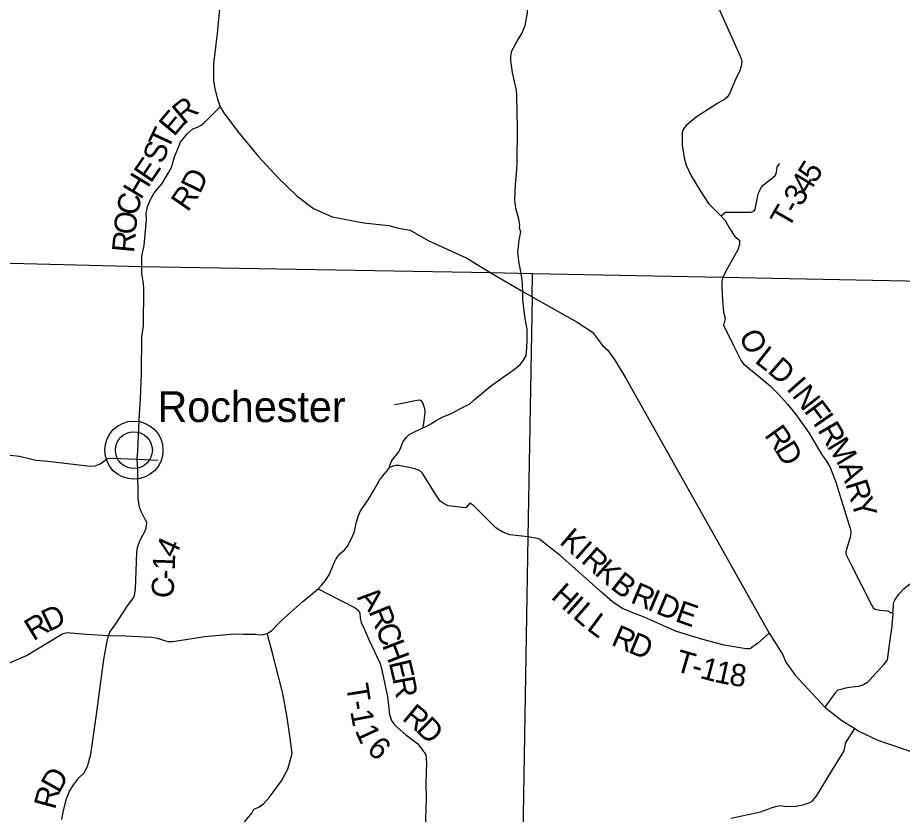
# Model space of a CAD drawing. Extents: x -22 to 431, y -18 to 160.
# Drawn here: x 324.965 to 327.228, y 151.4 to 153.438 of the extents above; entities that cross this region are included whole.
import ezdxf

# ---------------------------------------------------------------- set-up
doc = ezdxf.new("R2010")
doc.units = 0
for name, color, linetype in [('GM_X_Adjacent_County', 7, 'Continuous'), ('GM_X_Adjacent_County_Text', 7, 'Continuous'), ('GM_X_City_Street', 7, 'Continuous'), ('GM_X_City_Street_Text', 7, 'Continuous'), ('GM_X_County_Road', 7, 'Continuous'), ('GM_X_County_ROW', 7, 'Continuous'), ('GM_X_Major_River_Text', 7, 'Continuous'), ('GM_X_Minor_River_Text', 7, 'Continuous'), ('GM_X_Township_Road', 7, 'Continuous')]:
    doc.layers.add(name, color=color, linetype=linetype)

msp = doc.modelspace()

# ---------------------------------------------------------------- linework, layer by layer
at = {"layer": 'GM_X_Adjacent_County_Text'}
for points in [[(326.2484, 152.8999), (326.2484, 152.9001), (326.2493, 152.9074), (326.2474, 152.9225), (326.2394, 152.9506), (326.2367, 152.9711), (326.2382, 153.0116), (326.2416, 153.0492), (326.2427, 153.0666), (326.2434, 153.1561), (326.2422, 153.238), (326.2407, 153.2521), (326.2308, 153.2979), (326.2262, 153.3275), (326.2262, 153.3396), (326.2289, 153.3537), (326.2425, 153.3783), (326.2546, 153.3973), (326.2633, 153.4182), (326.2689, 153.4508), (326.2715, 153.5187)], [(326.7581, 153.4619), (326.8097, 153.3476), (326.8159, 153.3333), (326.8171, 153.3272), (326.8167, 153.3196), (326.8131, 153.3044), (326.8015, 153.28), (326.7854, 153.2431), (326.7802, 153.2351), (326.7734, 153.229), (326.756, 153.2194), (326.7009, 153.1837), (326.6752, 153.1623), (326.6685, 153.1539), (326.6644, 153.144), (326.665, 153.1125), (326.6698, 153.0799), (326.6748, 153.0609), (326.6875, 153.0337), (326.7114, 152.994), (326.7321, 152.9626), (326.7634, 152.9314), (326.7745, 152.9193), (326.7868, 152.8978), (326.7998, 152.8785), (326.8111, 152.8687), (326.8111, 152.8582), (326.8071, 152.8443), (326.7762, 152.7899), (326.769, 152.7734), (326.7658, 152.7641), (326.7659, 152.7611)], [(325.2831, 152.7841), (325.283, 152.7847), (325.2828, 152.8006), (325.2831, 152.828), (325.2889, 152.8551), (325.295, 152.9211), (325.2943, 152.9374), (325.2977, 152.9549), (325.3052, 152.9731), (325.3139, 152.9883), (325.3238, 153.0008), (325.3344, 153.0137), (325.3521, 153.0433), (325.3589, 153.0551), (325.3665, 153.082), (325.382, 153.1196), (325.399, 153.1409), (325.4134, 153.1538), (325.4255, 153.1584), (325.4342, 153.1633), (325.4422, 153.1694), (325.4607, 153.1876), (325.4834, 153.2104)], [(326.2571, 152.7373), (326.2557, 152.7679), (326.2533, 152.7838), (326.2475, 152.8104), (326.2447, 152.8372), (326.248, 152.8688), (326.2518, 152.8903), (326.2484, 152.8999)], [(325.1975, 151.8578), (325.2009, 151.8658), (325.216, 151.8878), (325.2448, 151.9307), (325.2618, 151.9543), (325.2644, 151.9596), (325.2663, 151.9759), (325.27, 152.07), (325.2719, 152.0825), (325.2776, 152.0996), (325.2931, 152.1285), (325.2946, 152.1379), (325.2953, 152.1467), (325.2915, 152.1546), (325.2809, 152.1747), (325.2771, 152.1857), (325.2733, 152.2088), (325.2725, 152.2828), (325.2709, 152.3086), (325.2724, 152.3298), (325.2765, 152.4243), (325.2791, 152.4611), (325.2821, 152.5282), (325.2824, 152.6215), (325.2872, 152.65), (325.2878, 152.7445), (325.2872, 152.7576), (325.2857, 152.7684), (325.2831, 152.7841)], [(326.7659, 152.7611), (326.7661, 152.747), (326.7676, 152.7151), (326.7702, 152.6846), (326.7743, 152.6689), (326.7704, 152.6513), (326.7961, 152.5991), (326.815, 152.5617), (326.8208, 152.5534), (326.836, 152.5406), (326.8601, 152.5214), (326.8902, 152.4962), (326.9112, 152.4751), (326.9338, 152.4494), (326.9552, 152.423), (326.9897, 152.3754), (327.0109, 152.3383), (327.0231, 152.3187), (327.0339, 152.304), (327.0431, 152.2873), (327.0574, 152.2502), (327.0947, 152.1313), (327.0959, 152.1233), (327.0952, 152.1116), (327.0852, 152.0785), (327.0834, 152.0712), (327.0834, 152.0655), (327.0953, 152.0417), (327.1501, 151.9345)], [(326.261, 152.6875), (326.2573, 152.7179), (326.2571, 152.7373)], [(325.1975, 151.8578), (325.2426, 151.8564), (325.2895, 151.8546), (325.3077, 151.8534), (325.3228, 151.8504), (325.3384, 151.8455), (325.3497, 151.8425), (325.3611, 151.8421), (325.4065, 151.8487), (325.4429, 151.8552), (325.491, 151.859), (325.5209, 151.8617), (325.5428, 151.8614), (325.5731, 151.8607), (325.5845, 151.8592), (325.5947, 151.8603), (325.603, 151.863), (325.6144, 151.8698), (325.6386, 151.8942), (325.6651, 151.9185), (325.6942, 151.9447), (325.7336, 151.977), (325.7426, 151.9865), (325.7529, 151.9979), (325.7616, 152.0131), (325.7755, 152.0454), (325.7797, 152.0537), (325.7831, 152.059), (325.7895, 152.0666), (325.8016, 152.078), (325.8088, 152.0864), (325.8175, 152.1027), (325.8258, 152.1213), (325.8322, 152.1482), (325.8368, 152.1646), (325.8417, 152.1763), (325.8614, 152.2044), (325.8757, 152.2276), (325.8859, 152.2454), (325.8908, 152.2553), (325.8984, 152.2655), (325.9098, 152.2777), (325.9166, 152.2876), (325.9169, 152.2929), (325.9226, 152.3054), (325.94, 152.3278), (325.9434, 152.3343), (325.9506, 152.3521), (325.9589, 152.3639), (325.9661, 152.3718), (325.982, 152.3791), (326.0024, 152.3893), (326.0134, 152.3943), (326.0357, 152.408), (326.0513, 152.4163), (326.0638, 152.4217), (326.0751, 152.4259), (326.0887, 152.4331), (326.0974, 152.4384), (326.1114, 152.4449), (326.1205, 152.4494), (326.1326, 152.4601), (326.1735, 152.4943), (326.2042, 152.5171), (326.2352, 152.538), (326.2507, 152.5505), (326.2575, 152.5596), (326.2657, 152.5742), (326.2676, 152.5933), (326.2686, 152.6144), (326.2686, 152.6411), (326.2633, 152.6684), (326.261, 152.6875)], [(324.9387, 152.32), (324.9698, 152.3164), (324.9983, 152.3097), (325.012, 152.3061), (325.042, 152.3033), (325.1513, 152.2912), (325.1637, 152.2914), (325.1762, 152.2966), (325.1889, 152.3063), (325.1949, 152.3102), (325.2073, 152.3116), (325.2709, 152.3086)], [(325.2709, 152.3086), (325.3234, 152.3062)], [(327.1501, 151.9345), (327.1503, 151.934), (327.1507, 151.9331), (327.1542, 151.9278), (327.1584, 151.9252), (327.1702, 151.9223), (327.1895, 151.9205), (327.1926, 151.9198), (327.1979, 151.9168), (327.2032, 151.9145), (327.2029, 151.9031), (327.1997, 151.8758), (327.1951, 151.8408), (327.19, 151.8017), (327.1886, 151.7956), (327.1799, 151.7822), (327.1446, 151.744), (327.1366, 151.7364), (327.1287, 151.7317), (327.1158, 151.7275), (327.0984, 151.7255), (327.0821, 151.7227), (327.0708, 151.7199), (327.0632, 151.7176), (327.0556, 151.7107), (327.0294, 151.6744)], [(324.9363, 151.7846), (324.9882, 151.8067), (325.0786, 151.8611), (325.082, 151.8626), (325.0919, 151.8656), (325.1407, 151.8608), (325.1975, 151.8578)], [(325.0783, 151.3868), (325.0824, 151.4096), (325.09, 151.4399), (325.0979, 151.4597), (325.1093, 151.4768), (325.1221, 151.4935), (325.135, 151.5064), (325.144, 151.5227), (325.1527, 151.5539), (325.167, 151.6552), (325.1854, 151.7964), (325.1941, 151.843), (325.1975, 151.8578)]]:
    msp.add_lwpolyline(points, dxfattribs=at)
at = {"layer": 'GM_X_County_Road'}
msp.add_lwpolyline([(326.0048, 151.5589), (326.0092, 151.5525), (326.0112, 151.5321), (326.0093, 151.4812), (326.0104, 151.4402), (326.0075, 151.362), (326.0046, 151.2439), (325.9988, 151.0556), (326.0007, 151.0484), (326.0114, 151.0379), (326.0437, 151.0196), (326.0464, 151.018), (326.05, 151.0153)], dxfattribs=at)
at = {"layer": 'GM_X_County_ROW'}
msp.add_lwpolyline([(325.4814, 153.4613), (325.4752, 153.3978), (325.466, 153.3204), (325.4665, 153.2778), (325.4693, 153.2562), (325.4762, 153.2293), (325.4834, 153.2104), (325.4929, 153.1945), (325.5278, 153.1479), (325.5792, 153.0851), (325.6322, 153.028), (325.6805, 152.9812), (325.722, 152.9503), (325.7699, 152.9289), (325.8508, 152.9137), (325.9146, 152.9064), (325.9396, 152.8997), (325.9692, 152.8949), (326.0152, 152.8678), (326.1137, 152.8228), (326.1756, 152.7856), (326.2571, 152.7373), (326.2813, 152.7241), (326.3958, 152.6588), (326.435, 152.6335), (326.4606, 152.5996), (326.4747, 152.5879), (326.4941, 152.5591), (326.5212, 152.5141), (326.8876, 151.8637), (326.9054, 151.8357), (326.9226, 151.8078), (326.9295, 151.7896), (326.9533, 151.7562), (326.9977, 151.7083), (327.0294, 151.6744), (327.0306, 151.6731), (327.0732, 151.6403), (327.1062, 151.6196), (327.1182, 151.6121), (327.1651, 151.59), (327.2594, 151.5577)], dxfattribs=at)
at = {"layer": 'GM_X_Major_River_Text'}
for p, q in [((325.2828, 152.8006), (324.4484, 152.8216)), ((326.1756, 152.7856), (325.2828, 152.8006)), ((326.282, 152.7832), (326.1756, 152.7856)), ((326.2813, 152.7241), (326.282, 152.7832)), ((326.769, 152.7734), (326.282, 152.7832)), ((327.8671, 152.7513), (326.769, 152.7734)), ((326.2813, 152.7241), (326.2703, 152.1098)), ((326.2703, 152.1098), (326.2096, 148.5516))]:
    msp.add_line(p, q, dxfattribs=at)
at = {"layer": 'GM_X_Minor_River_Text'}
for points in [[(326.7634, 152.9314), (326.7756, 152.9404), (326.7828, 152.9408), (326.8392, 152.9408), (326.8434, 152.9416), (326.8479, 152.9432), (326.8513, 152.947), (326.8546, 152.9648), (326.8572, 152.9793), (326.8601, 152.9892), (326.8668, 153.0036), (326.8728, 153.0101), (326.8917, 153.025), (326.9022, 153.0346), (326.906, 153.0418), (326.9081, 153.0559), (326.9104, 153.0604), (326.9149, 153.0654)], [(326.0024, 152.3893), (326.0051, 152.4068), (326.0073, 152.4277), (326.0069, 152.4375), (326.0016, 152.4527), (325.9971, 152.4584), (325.9914, 152.4599), (325.9732, 152.4564), (325.949, 152.4511), (325.9289, 152.448)], [(326.4875, 151.9429), (326.4865, 151.9435), (326.4583, 151.9683), (326.353, 152.0621), (326.3138, 152.0931), (326.3, 152.1041), (326.2908, 152.107), (326.2703, 152.1098), (326.2241, 152.115), (326.2062, 152.1219), (326.1878, 152.1329), (326.1308, 152.1904), (326.1216, 152.1962), (326.1117, 152.1845), (326.0957, 152.1857), (326.0665, 152.1897), (326.0558, 152.1945), (326.0462, 152.2011), (326.0357, 152.2165), (325.9999, 152.2735), (325.9964, 152.2772), (325.9903, 152.2805), (325.9785, 152.2849), (325.9397, 152.2929), (325.9322, 152.2928), (325.9269, 152.2919), (325.9166, 152.2876)], [(327.2032, 151.9145), (327.2054, 151.9335), (327.2053, 151.9415), (327.2083, 151.9483), (327.2188, 151.9636), (327.2327, 151.9777), (327.2689, 152.0069), (327.3342, 152.0525), (327.4313, 152.1124), (327.4396, 152.1162), (327.4457, 152.1178), (327.459, 152.1164), (327.4727, 152.1115)], [(325.7336, 151.977), (325.7571, 151.9649), (325.8282, 151.9287), (325.8331, 151.9253), (325.8377, 151.9208), (325.8404, 151.9147), (325.8412, 151.903), (325.8436, 151.8909), (325.8517, 151.875), (325.8636, 151.8474), (325.8913, 151.7873), (325.8951, 151.7763), (325.8995, 151.7566), (325.9108, 151.7017), (325.9165, 151.6558), (325.9215, 151.6399), (325.9288, 151.6289), (325.9581, 151.6037), (325.9886, 151.5805), (326.0008, 151.5646), (326.0026, 151.562), (326.0048, 151.5589)], [(326.8876, 151.8637), (326.8571, 151.8373), (326.8431, 151.8266), (326.839, 151.8235), (326.828, 151.8238), (326.7721, 151.8333), (326.7178, 151.8477), (326.6505, 151.8677), (326.6137, 151.8842), (326.5676, 151.9044), (326.5389, 151.9159), (326.5124, 151.9268), (326.4875, 151.9429)], [(325.5425, 151.3773), (325.5639, 151.4029), (325.5695, 151.4132), (325.582, 151.4182), (325.5951, 151.4278), (325.609, 151.4443), (325.6398, 151.4855), (325.6566, 151.516), (325.6669, 151.5559), (325.6625, 151.595), (325.6549, 151.648), (325.6431, 151.709), (325.6162, 151.8158), (325.603, 151.863)], [(326.8695, 151.408), (326.8818, 151.4125), (326.8947, 151.4172), (326.9045, 151.4199), (326.9155, 151.4223), (326.9273, 151.4212), (326.9504, 151.4199), (326.9743, 151.4242), (326.991, 151.4304), (326.9985, 151.4354), (327.009, 151.4487), (327.0473, 151.5117), (327.0743, 151.554), (327.0787, 151.5624), (327.0813, 151.575), (327.0828, 151.5822), (327.088, 151.5913), (327.1062, 151.6196)], [(326.7902, 151.3907), (326.8095, 151.3949), (326.8409, 151.4016), (326.8682, 151.4075), (326.8695, 151.408)]]:
    msp.add_lwpolyline(points, dxfattribs=at)
at = {"layer": 'GM_X_Township_Road'}
for radius in [0.0744, 0.0472]:
    msp.add_circle((325.2625, 152.3318), radius, dxfattribs=at)

# ---------------------------------------------------------------- texts
at = {"layer": 'GM_X_Adjacent_County'}
msp.add_text('Rochester', height=0.07891, rotation=0, dxfattribs=at).set_placement((325.3229, 152.4037))
at = {"layer": 'GM_X_City_Street'}
for s, rotation, p in [('R', 39.7046, (325.3905, 153.1627)), ('E', 50.0035, (325.3651, 153.132)), ('T', 65.0949, (325.3493, 153.0968)), ('S', 70.4668, (325.337, 153.062)), ('E', 55.5539, (325.3056, 153.0126)), ('H', 58.8932, (325.2803, 152.9705)), ('D', 63.867, (325.4311, 152.9853)), ('C', 77.0893, (325.2716, 152.9294)), ('R', 55.4038, (325.4001, 152.9391)), ('O', 84.3006, (325.267, 152.8815)), ('R', 84.5197, (325.2625, 152.8351)), ('O', 295.5501, (326.8086, 152.6249)), ('L', 321.8164, (326.8478, 152.5577)), ('D', 318.9416, (326.8806, 152.5319)), ('I', 311.3269, (326.9292, 152.488)), ('N', 307.8076, (326.944, 152.4712)), ('F', 306.8214, (326.9745, 152.4319)), ('I', 304.7401, (326.9972, 152.4017)), ('R', 305.6606, (326.8733, 152.3699)), ('R', 300.1665, (327.0098, 152.3835)), ('D', 301.1705, (326.8999, 152.333)), ('M', 301.1074, (327.0338, 152.3423)), ('A', 290.1723, (327.0644, 152.2921)), ('R', 287.6462, (327.0815, 152.2458)), ('Y', 287.3682, (327.0956, 152.2014)), ('4', 65.4531, (325.367, 152.0528)), ('1', 87.9284, (325.367, 152.0236)), ('-', 88.0035, (325.3662, 152.0003)), ('C', 86.0979, (325.363, 151.9516)), ('D', 25.5354, (325.0439, 151.8659)), ('R', 31.271, (325.0053, 151.8424)), ('D', 60.8601, (325.0714, 151.4518)), ('R', 74.6904, (325.0605, 151.4102))]:
    msp.add_text(s, height=0.0568, rotation=rotation, dxfattribs=at).set_placement(p)
at = {"layer": 'GM_X_City_Street_Text'}
for s, rotation, p in [('5', 57.6653, (327.0051, 153.0124)), ('4', 58.4392, (326.9869, 152.9827)), ('3', 59.1674, (326.9691, 152.9528)), ('T', 59.8889, (326.9361, 152.8961)), ('-', 59.6936, (326.9574, 152.9328)), ('K', 319.471, (326.3484, 152.0942)), ('I', 318.4631, (326.3862, 152.0619)), ('R', 318.3717, (326.4036, 152.0464)), ('K', 318.4299, (326.4386, 152.0154)), ('B', 322.0612, (326.4789, 151.9797)), ('H', 318.286, (326.327, 151.9542)), ('R', 337.4897, (326.5299, 151.9428)), ('A', 310.5677, (325.8319, 151.9534)), ('I', 336.8301, (326.5728, 151.925)), ('I', 318.405, (326.3644, 151.9208)), ('D', 337.2511, (326.5947, 151.9156)), ('E', 340.5943, (326.6441, 151.895)), ('R', 291.9942, (325.8619, 151.9196)), ('L', 318.9688, (326.3823, 151.9049)), ('L', 323.4194, (326.4181, 151.874)), ('C', 291.7384, (325.8793, 151.8764)), ('R', 336.6099, (326.4805, 151.8345)), ('D', 337.3312, (326.5241, 151.8156)), ('H', 290.9978, (325.8965, 151.8332)), ('T', 343.795, (326.6435, 151.7679)), ('E', 283.5134, (325.9139, 151.7884)), ('1', 344.8453, (326.7079, 151.7493)), ('1', 347.8662, (326.7448, 151.7394)), ('8', 351.6416, (326.7831, 151.7313)), ('-', 343.998, (326.6846, 151.756)), ('R', 280.7136, (325.9237, 151.7478)), ('T', 278.972, (325.805, 151.7302)), ('-', 279.2084, (325.8117, 151.688)), ('R', 320.5197, (325.9461, 151.6431)), ('1', 280.5375, (325.8156, 151.6635)), ('D', 315.6182, (325.9812, 151.6143)), ('1', 294.8043, (325.8267, 151.6144)), ('6', 317.4092, (325.8557, 151.5631))]:
    msp.add_text(s, height=0.0568, rotation=rotation, dxfattribs=at).set_placement(p)

doc.saveas('drawing.dxf')
